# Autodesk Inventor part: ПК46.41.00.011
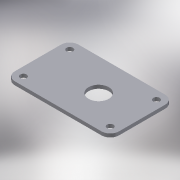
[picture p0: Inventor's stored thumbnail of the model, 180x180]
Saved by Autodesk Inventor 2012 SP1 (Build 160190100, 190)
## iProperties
Created: 2005-05
Part Number: ПК46.41.00.011
Material: Steel, Mild
Document SubType Name: Листовой материал
Designer: PVitaliy
Manufacturer: Standard
Standards Organization: Custom
Description: Плита
Density: 7.86 g/cm^3
Sheet Metal Rule: По умолчанию
Author: PVitaliy
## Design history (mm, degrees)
node "Грань1"
  sketch "Эскиз2"
    geometry: L1 (15, 0)-(165, 0); L2 (180, 15)-(180, 95); L3 (165, 110)-(15, 110); L4 (0, 95)-(0, 15); L5 (15, 95)-(165, 95); L6 (165, 95)-(165, 15); L7 (165, 15)-(15, 15); L8 (15, 15)-(15, 95); C1 r 5.5 at (15, 95); C2 r 5.5 at (15, 15); C3 r 5.5 at (165, 95); C4 r 5.5 at (165, 15); A1 r 15 centre (15, 95) between (15, 110) and (0, 95); A2 r 15 centre (15, 15) between (0, 15) and (15, 0); A3 r 15 centre (165, 15) between (165, 0) and (180, 15); A4 r 15 centre (165, 95) between (180, 95) and (165, 110)
    constraints: 16 end point, 8 centre point, 8 point on circle, 7 coincident, 4 parallel, 4 tangent, 3 equal radius, 2 horizontal, 2 perpendicular
    dimensions: "d0" = 150 distance of L5.start L5.end; "d1" = 80 distance of L5.end L6.end; "d2" = 15 distance between parallel lines of L8 L4; "d3" = 15 distance between parallel lines of L2 L6; "d4" = 15 distance between parallel lines of L1 L7; "d5" = 15 distance between parallel lines of L5 L3; "d6" = 11 diameter of C1
node "РабПлоскость1"
hole "Отверстие2" diameter "d19" = 35; stored, may be unused: countersink angle "d23" = 90 deg, drill point angle "d25" = 118 deg; dims "d17" = 75, "d18" = 55, "d20" = 6, "d21" = 4, "d22" = 2, "d24" = 6 (= Толщина)
body "Solid1"
feature "Плакирование1" dims "Толщина" = 6
other parameters: "Радиус_гибки" = 6 (= Толщина), "Ширина_просечки" = 6 (= Толщина), "Глубина_просечки" = 3 (= 0.5 x Толщина), "Размер_высечки" = 24 (= 4 x Толщина), "Зазор_стыка" = 0.01, "Минимальный_остаток" = 12 (= 2 x Толщина), "Радиус_перехода" = 6 (= Радиус_гибки), "d7" = 6 (= Радиус_гибки), "JacobiRadiusSize" = 6 (= Толщина), "GapSize" = 6 (= Толщина)
